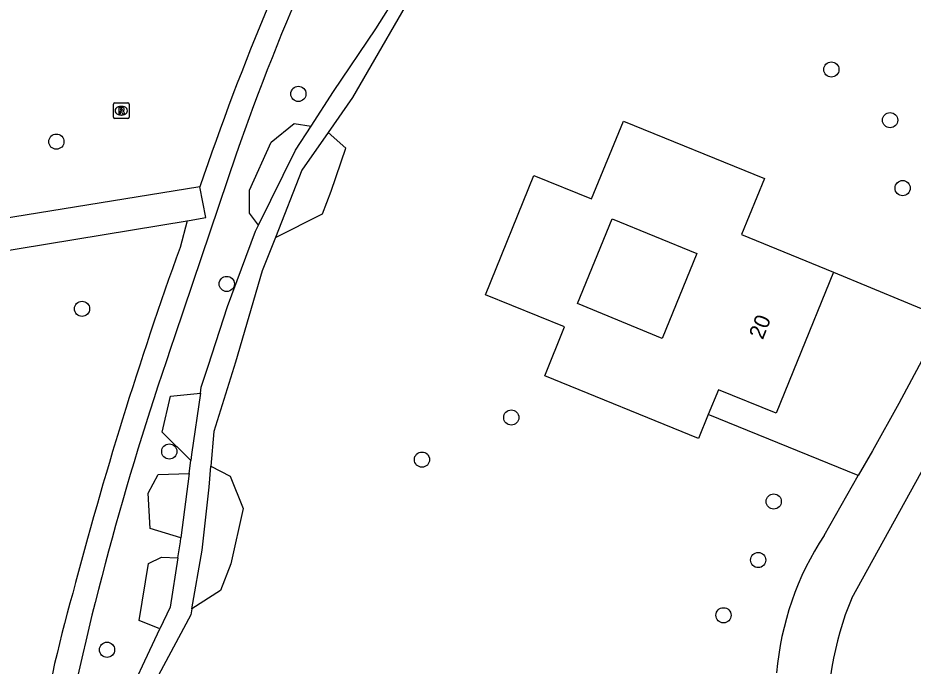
# Model space of a CAD drawing. Extents: x 156664 to 157568, y 383571 to 384421.
# Drawn here: x 156792.3 to 156849.9, y 384130.7 to 384172.4 of the extents above; entities that cross this region are included whole.
import ezdxf

# ---------------------------------------------------------------- set-up
doc = ezdxf.new("R2010")
doc.units = 0
for name, color, linetype in [('IMGEO_Boom', 7, 'Continuous'), ('IMGEO_Groenvoorziening', 7, 'Continuous'), ('IMGEO_Pand', 7, 'Continuous'), ('IMGEO_Pand_nummerreeks', 7, 'Continuous'), ('IMGEO_Rijbaan_lokaal_gesloten', 7, 'Continuous'), ('IMGEO_Rioolput', 7, 'Continuous'), ('IMGEO_Voetpad_halfverhard', 7, 'Continuous'), ('IMGEO_Voetpad_open', 7, 'Continuous'), ('IMGEO_Waterloop', 7, 'Continuous')]:
    doc.layers.add(name, color=color, linetype=linetype)

msp = doc.modelspace()

# ---------------------------------------------------------------- linework, layer by layer
at = {"layer": 'IMGEO_Boom'}
for centre in [(156844.648, 384169.051), (156810.367, 384167.481), (156848.426, 384165.795), (156794.802, 384164.414), (156849.235, 384161.426), (156805.76, 384155.263), (156796.451, 384153.666), (156824.062, 384146.674), (156802.065, 384144.492), (156818.318, 384143.968), (156840.942, 384141.274), (156839.944, 384137.513), (156837.712, 384133.959), (156798.059, 384131.742)]:
    msp.add_circle(centre, 0.489, dxfattribs=at)
at = {"layer": 'IMGEO_Groenvoorziening'}
for points in [[(156807.799, 384159.043), (156807.216, 384159.825), (156807.227, 384161.3), (156808.616, 384164.372), (156810.1, 384165.583), (156811.182, 384165.417)], [(156808.898, 384158.258), (156811.915, 384159.779), (156812.477, 384161.225), (156813.426, 384164.002), (156812.277, 384165.004)], [(156844.783, 384156.013), (156851.936, 384153.054)], [(156803.445, 384143.917), (156801.598, 384145.733), (156802.145, 384148.057), (156804.066, 384148.241)], [(156846.369, 384142.937), (156836.731, 384146.86)], [(156804.743, 384143.542), (156805.981, 384142.907), (156806.807, 384140.817), (156806.034, 384137.271), (156805.363, 384135.548), (156803.52, 384134.378)], [(156802.813, 384138.949), (156800.842, 384139.544), (156800.714, 384141.81), (156801.341, 384143.016), (156803.338, 384143.079)], [(156801.456, 384133.079), (156800.122, 384133.614), (156800.735, 384137.294), (156801.559, 384137.705), (156802.616, 384137.643)]]:
    msp.add_lwpolyline(points, dxfattribs=at)
at = {"layer": 'IMGEO_Pand'}
for points in [[(156836.731, 384146.86), (156836.101, 384145.316), (156826.211, 384149.347), (156827.495, 384152.496), (156822.401, 384154.572), (156825.514, 384162.245), (156829.227, 384160.73), (156831.271, 384165.739), (156840.338, 384162.041), (156838.86, 384158.44), (156844.783, 384156.013)], [(156833.763, 384151.763), (156828.313, 384154.006), (156830.556, 384159.455), (156836.005, 384157.212), (156833.763, 384151.763)], [(156844.783, 384156.013), (156842.447, 384150.269), (156841.097, 384146.948), (156837.382, 384148.459), (156836.731, 384146.86)]]:
    msp.add_lwpolyline(points, dxfattribs=at)
at = {"layer": 'IMGEO_Rijbaan_lokaal_gesloten'}
for points in [[(156851.936, 384153.054), (156848.989, 384147.571), (156847.291, 384144.543), (156846.369, 384142.937)], [(156845.957, 384135.061), (156854.995, 384151.422)], [(156844.181, 384139.094), (156846.369, 384142.937)]]:
    msp.add_lwpolyline(points, dxfattribs=at)
for centre, radius, start, end in [((156860.109, 384128.64), 19.052, 146.72015, 175.10267), ((156864.498, 384127.333), 20.087, 157.37322, 183.71037)]:
    msp.add_arc(centre, radius, start, end, dxfattribs=at)
at = {"layer": 'IMGEO_Rioolput'}
for p, q in [((156798.476, 384165.977), (156798.476, 384166.829)), ((156798.551, 384166.903), (156799.403, 384166.903)), ((156798.964, 384166.683), (156798.989, 384166.683)), ((156799.477, 384166.829), (156799.477, 384165.977)), ((156799.403, 384165.903), (156798.551, 384165.903)), ((156798.987, 384166.123), (156798.962, 384166.123))]:
    msp.add_line(p, q, dxfattribs=at)
for points in [[(156798.476, 384165.977), (156798.476, 384166.829)], [(156798.551, 384166.903), (156799.403, 384166.903)], [(156799.065, 384166.601), (156798.813, 384166.603), (156798.813, 384166.203)], [(156798.991, 384166.522), (156798.937, 384166.522), (156798.937, 384166.441)], [(156798.937, 384166.441), (156798.989, 384166.441)], [(156799.477, 384166.829), (156799.477, 384165.977)], [(156799.403, 384165.903), (156798.551, 384165.903)], [(156798.813, 384166.203), (156798.937, 384166.203), (156798.937, 384166.365), (156798.948, 384166.365)], [(156798.995, 384166.336), (156799.066, 384166.203), (156799.206, 384166.203), (156799.141, 384166.329)]]:
    msp.add_lwpolyline(points, dxfattribs=at)
for centre, radius, start, end in [((156798.553, 384166.827), 0.0765, 91.55205, 178.44795), ((156798.553, 384166.827), 0.0765, 91.55205, 178.44795), ((156798.973, 384166.63), 0.19, 274.7715, 282.96867), ((156798.997, 384166.426), 0.0964, 77.00612, 93.18647), ((156799.011, 384166.483), 0.0378, 276.66336, 79.67722), ((156799.064, 384166.491), 0.109, 350.36119, 89.41601), ((156799.062, 384166.491), 0.112, 277.58423, 350.98172), ((156799.046, 384166.276), 0.108, 29.51342, 73.79051), ((156799.401, 384166.827), 0.0765, 1.55205, 88.44795), ((156799.401, 384166.827), 0.0765, 1.55205, 88.44795), ((156798.553, 384165.979), 0.0765, 181.55205, 268.44795), ((156798.553, 384165.979), 0.0765, 181.55205, 268.44795), ((156798.947, 384166.312), 0.0533, 26.02933, 88.69889), ((156799.401, 384165.979), 0.0765, 271.55205, 358.44795), ((156799.401, 384165.979), 0.0765, 271.55205, 358.44795)]:
    msp.add_arc(centre, radius, start, end, dxfattribs=at)
for centre, major_axis, ratio, start_param, end_param in [((156798.963, 384166.403), (-0.387, 0.002), 0.722429, 4.712389, 7.853982), ((156798.988, 384166.403), (-0.39, 0.002), 0.717154, 1.570796, 4.712389)]:
    msp.add_ellipse(centre, major_axis=major_axis, ratio=ratio, start_param=start_param, end_param=end_param, dxfattribs=at)
at = {"layer": 'IMGEO_Voetpad_halfverhard'}
for points in [[(156806.371, 384163.618), (156802.431, 384151.925)], [(156803.211, 384159.313), (156802.755, 384157.61)]]:
    msp.add_lwpolyline(points, dxfattribs=at)
for centre, radius, start, end in [((156948.827, 384114.152), 150.8, 150.81819, 160.85094), ((156974.026, 384103.917), 179.483, 153.24763, 161.28416), ((157049.817, 384068.751), 262.556, 160.21819, 165.30099), ((156990.865, 384086.149), 199.584, 160.75765, 168.58605), ((156888.14, 384109.263), 95.909, 164.20283, 170.57996)]:
    msp.add_arc(centre, radius, start, end, dxfattribs=at)
at = {"layer": 'IMGEO_Voetpad_open'}
for points in [[(156804.034, 384161.508), (156784.051, 384158.265), (156799.42, 384200.59), (156813.755, 384184.708)], [(156803.211, 384159.313), (156803.344, 384159.335), (156804.417, 384159.527), (156804.034, 384161.508)], [(156768.247, 384114.722), (156783.275, 384156.048), (156803.211, 384159.313)]]:
    msp.add_lwpolyline(points, dxfattribs=at)
at = {"layer": 'IMGEO_Waterloop'}
for points in [[(156811.182, 384165.417), (156812.625, 384167.645), (156815.349, 384171.665), (156816.776, 384173.954), (156817.991, 384177.189), (156818.056, 384177.384)], [(156819.023, 384176.755), (156818.415, 384175.166), (156813.843, 384167.26), (156812.277, 384165.004)], [(156807.799, 384159.043), (156810.18, 384163.871), (156811.182, 384165.417)], [(156812.277, 384165.004), (156810.597, 384162.583), (156808.898, 384158.258)], [(156804.066, 384148.241), (156804.123, 384148.633), (156804.561, 384149.979), (156805.808, 384153.809), (156807.611, 384158.662), (156807.799, 384159.043)], [(156808.898, 384158.258), (156808.049, 384156.096), (156806.328, 384150.229), (156804.93, 384145.785), (156804.743, 384143.542)], [(156804.066, 384148.241), (156803.493, 384144.297), (156803.445, 384143.917)], [(156803.338, 384143.079), (156803.445, 384143.917)], [(156803.52, 384134.378), (156804.184, 384138.14), (156804.63, 384142.189), (156804.743, 384143.542)], [(156803.338, 384143.079), (156802.813, 384138.949)], [(156802.616, 384137.643), (156802.78, 384138.691), (156802.813, 384138.949)], [(156802.616, 384137.643), (156802.123, 384134.492), (156801.456, 384133.079)], [(156803.52, 384134.378), (156803.451, 384133.987), (156801.041, 384129.502), (156799.383, 384124.962)], [(156798.107, 384125.917), (156800.34, 384130.718), (156801.456, 384133.079)]]:
    msp.add_lwpolyline(points, dxfattribs=at)

# ---------------------------------------------------------------- texts
at = {"layer": 'IMGEO_Pand_nummerreeks'}
msp.add_text('20', height=1, rotation=68.37518, dxfattribs=at).set_placement((156840.237, 384151.636))

doc.saveas('drawing.dxf')
